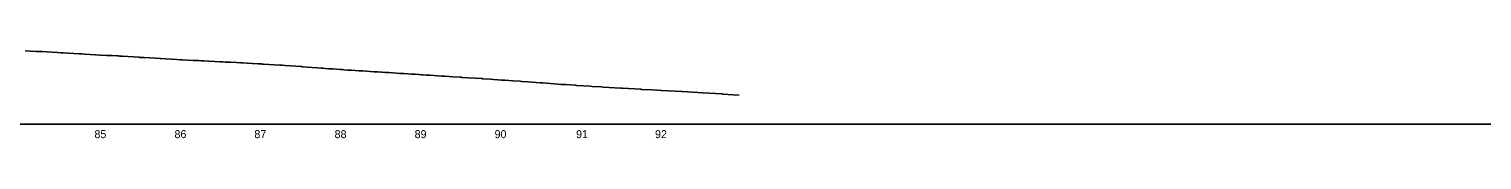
# Model space of a CAD drawing. Extents: x 579185 to 595036, y -53221 to -44640.
# Drawn here: x 586699 to 588514, y -45018 to -44908 of the extents above; entities that cross this region are included whole.
import ezdxf

# ---------------------------------------------------------------- set-up
doc = ezdxf.new("R2010")
doc.units = 0
for name, color, linetype in [('Exist Profile Cell', 7, 'Continuous'), ('Exist Vertical Profile Ground Line', 7, 'Continuous'), ('Exist Vertical Profile Horizontal Axis Label Major', 7, 'Continuous')]:
    doc.layers.add(name, color=color, linetype=linetype)

msp = doc.modelspace()

# ---------------------------------------------------------------- linework, layer by layer
at = {"layer": 'Exist Profile Cell'}
msp.add_line((579221, -45000), (594884.8, -45000), dxfattribs=at)
at = {"layer": 'Exist Vertical Profile Ground Line'}
for points in [[(586693.8, -44908.3), (586700.6, -44908.7), (586707.3, -44909.1), (586713.6, -44909.4), (586714.1, -44909.5), (586715.2, -44909.5), (586720.9, -44909.8), (586727.6, -44910.2), (586734.4, -44910.6), (586738.8, -44910.8), (586739.9, -44910.9), (586741.2, -44911), (586747.9, -44911.4)], [(586747.9, -44911.4), (586754.7, -44911.7), (586761.5, -44912.1), (586764, -44912.3), (586764.6, -44912.3), (586768.2, -44912.5), (586775, -44912.9), (586781.8, -44913.3), (586788, -44913.7), (586788.5, -44913.7), (586795.3, -44914.1), (586802.1, -44914.4), (586808.8, -44914.8), (586810.3, -44914.9), (586812, -44915), (586815.6, -44915.2), (586822.4, -44915.7), (586829.1, -44916.1), (586836.2, -44916.5), (586837.1, -44916.6), (586842.7, -44916.9), (586849.4, -44917.3), (586856.2, -44917.8), (586862.3, -44918.1), (586863, -44918.2), (586869.7, -44918.5), (586876.5, -44918.9), (586883.3, -44919.3), (586888, -44919.5), (586889.2, -44919.6), (586890, -44919.6), (586896.8, -44920), (586903.6, -44920.4), (586910.3, -44920.7), (586913.8, -44920.9), (586915.9, -44921), (586917.1, -44921.1), (586923.9, -44921.4), (586930.6, -44921.8), (586937.4, -44922.1), (586938.5, -44922.2), (586940.6, -44922.3), (586944.2, -44922.5), (586950.9, -44922.8), (586957.7, -44923.2), (586963.3, -44923.5), (586964.5, -44923.5), (586965.2, -44923.6), (586971.2, -44923.9), (586978, -44924.3), (586984.8, -44924.6), (586988.5, -44924.9), (586990.1, -44925), (586991.5, -44925), (586998.3, -44925.4), (587005.1, -44925.9), (587011.8, -44926.3), (587013.7, -44926.4), (587015.1, -44926.5), (587018.6, -44926.7), (587025.4, -44927.2), (587032.1, -44927.7), (587038.6, -44928.2), (587038.9, -44928.2), (587040.4, -44928.3), (587045.7, -44928.7), (587052.4, -44929.2), (587059.2, -44929.7), (587063.5, -44930.1), (587063.9, -44930.1), (587065.8, -44930.2), (587068.6, -44930.4), (587073.3, -44930.8), (587078, -44931.1), (587082.7, -44931.4), (587087.3, -44931.7), (587088.7, -44931.8), (587090.2, -44931.9), (587092, -44932.1), (587096.7, -44932.4), (587101.4, -44932.7), (587106.1, -44933), (587110.8, -44933.3), (587113.8, -44933.5), (587114.7, -44933.6), (587115.5, -44933.6), (587120.2, -44933.9), (587124.8, -44934.2), (587129.5, -44934.5), (587134.2, -44934.8), (587138.9, -44935.1), (587139.9, -44935.2), (587143.6, -44935.4), (587148.3, -44935.7), (587153, -44936), (587157.7, -44936.3), (587162.3, -44936.6), (587163.9, -44936.7), (587165.1, -44936.8), (587167, -44936.9), (587171.7, -44937.2)], [(587171.7, -44937.2), (587176.4, -44937.5), (587181.1, -44937.8), (587185.8, -44938.1), (587188.9, -44938.3), (587190.1, -44938.3), (587190.5, -44938.4), (587195.2, -44938.7), (587199.8, -44939), (587209.2, -44939.6), (587213.9, -44939.9), (587214.9, -44939.9), (587218.6, -44940.2), (587228, -44940.8), (587237.3, -44941.4), (587238.8, -44941.5), (587239.8, -44941.6), (587246.7, -44942), (587256.1, -44942.6), (587263.7, -44943.1), (587264.8, -44943.2), (587265.5, -44943.3), (587274.8, -44943.9), (587278.8, -44944.2), (587284.2, -44944.5), (587289, -44944.9), (587289.7, -44944.9), (587293.6, -44945.2), (587303, -44945.8), (587312.3, -44946.5), (587314.2, -44946.6), (587321.7, -44947.2), (587337.5, -44948.3), (587339, -44948.4), (587340.5, -44948.6), (587359.2, -44950), (587363.4, -44950.3), (587363.8, -44950.3), (587369.1, -44950.7), (587381.5, -44951.5), (587382.6, -44951.6), (587399.6, -44952.7), (587402.1, -44952.8), (587413.3, -44953.5), (587415.9, -44953.7), (587438.2, -44955.1), (587440, -44955.2), (587463.1, -44956.5), (587464, -44956.6), (587477.4, -44957.3), (587488.5, -44957.9), (587489.1, -44958), (587513.9, -44959.4), (587514.8, -44959.4), (587534.2, -44960.5), (587539.5, -44960.9), (587539.9, -44960.9), (587564.5, -44962.3), (587565.6, -44962.4), (587578.5, -44963.5), (587585.8, -44963.9)]]:
    msp.add_lwpolyline(points, dxfattribs=at)

# ---------------------------------------------------------------- texts
at = {"layer": 'Exist Vertical Profile Horizontal Axis Label Major'}
for s, p in [('85', (586780.4, -45017.5)), ('86', (586880.4, -45017.5)), ('87', (586980.2, -45017.5)), ('88', (587080.4, -45017.5)), ('89', (587180.4, -45017.5)), ('90', (587280.3, -45017.5)), ('91', (587382.1, -45017.5)), ('92', (587480.7, -45017.5))]:
    msp.add_text(s, height=10, dxfattribs=at).set_placement(p)

doc.saveas('drawing.dxf')
